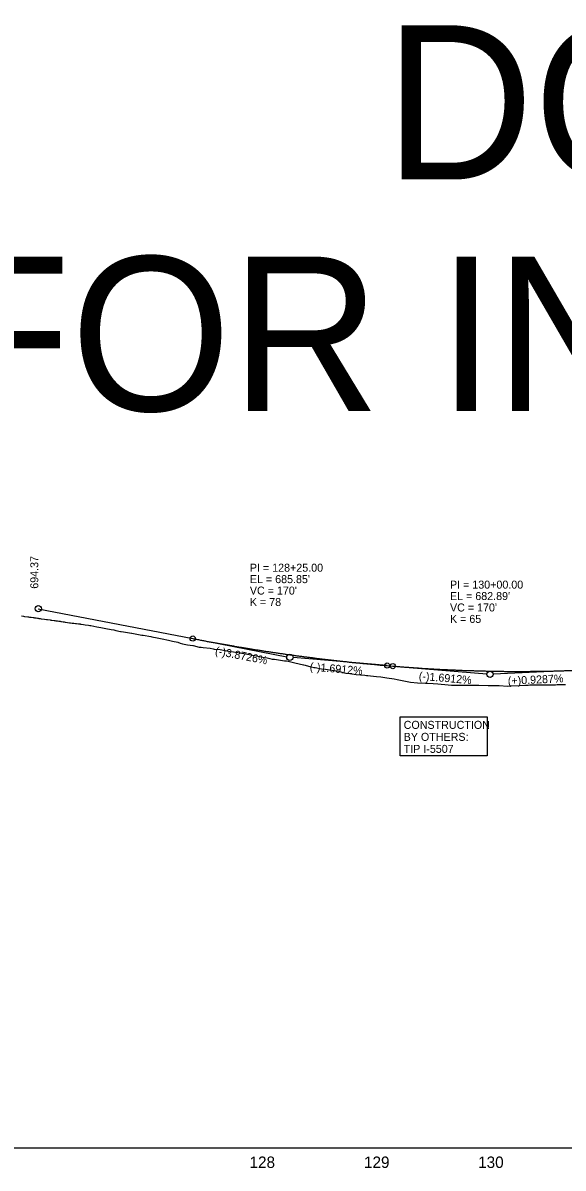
# Model space of a CAD drawing. Extents: x 1518255 to 1527303, y 471773 to 504546.
# Drawn here: x 1519662 to 1520134, y 497627 to 498629 of the extents above; entities that cross this region are included whole.
import ezdxf

# ---------------------------------------------------------------- set-up
doc = ezdxf.new("R2010")
doc.units = 0
for name, color, linetype in [('Default', 7, 'Continuous'), ('Exist Profile Cell', 7, 'Continuous'), ('Exist Vertical Profile Ground Line', 7, 'Continuous'), ('Exist Vertical Profile Horizontal Axis Label Major', 7, 'Continuous'), ('Prop Grid Mask', 7, 'Continuous'), ('Prop Vertical Profile Curve Label', 7, 'Continuous'), ('Prop Vertical Profile Grade Label', 7, 'Continuous'), ('Prop VPI Label', 7, 'Continuous')]:
    doc.layers.add(name, color=color, linetype=linetype)

msp = doc.modelspace()

# ---------------------------------------------------------------- linework, layer by layer
at = {"layer": 'Exist Profile Cell'}
msp.add_line((1519570.4, 497645), (1521670.4, 497645), dxfattribs=at)
at = {"layer": 'Exist Vertical Profile Ground Line'}
msp.add_lwpolyline([(1519660.8, 498110.5), (1519662.4, 498110.2), (1519663.3, 498110.1), (1519666.2, 498109.7), (1519666.7, 498109.7), (1519667.6, 498109.5), (1519669.1, 498109.3), (1519670.8, 498109.1), (1519671.5, 498109), (1519672, 498108.9), (1519673.6, 498108.7), (1519674.8, 498108.5), (1519675.2, 498108.5), (1519675.8, 498108.4), (1519676.5, 498108.3), (1519677, 498108.2), (1519677.8, 498108.1), (1519680.8, 498107.7), (1519682.5, 498107.4), (1519683.5, 498107.3), (1519685.7, 498107), (1519686.4, 498106.9), (1519687.3, 498106.8), (1519689.3, 498106.5), (1519689.8, 498106.4), (1519690.7, 498106.3), (1519691.7, 498106.2), (1519692.2, 498106.1), (1519693.5, 498105.9), (1519694.4, 498105.8), (1519695.1, 498105.7), (1519695.7, 498105.6), (1519697.2, 498105.4), (1519698, 498105.3), (1519699, 498105.1), (1519700.8, 498104.9), (1519702.7, 498104.6), (1519703.3, 498104.6), (1519703.7, 498104.5), (1519704.9, 498104.3), (1519705.7, 498104.3), (1519706.3, 498104.2), (1519706.6, 498104.1), (1519707.9, 498104), (1519708.9, 498103.8), (1519710.7, 498103.6), (1519711, 498103.6), (1519711.9, 498103.5), (1519712.3, 498103.4), (1519712.9, 498103.2), (1519715, 498103), (1519716.5, 498102.8), (1519719.2, 498102.3), (1519720.5, 498102.2), (1519721.2, 498102), (1519726.7, 498101), (1519730.1, 498100.3), (1519734.6, 498099.5), (1519739, 498098.6), (1519741.4, 498098.2), (1519743.2, 498097.9), (1519747.4, 498096.9), (1519748, 498096.8), (1519750, 498096.6), (1519756.9, 498095.3), (1519757.3, 498095.4), (1519764.4, 498094), (1519765.8, 498093.8), (1519767, 498093.6), (1519773.7, 498092.4), (1519774.8, 498092.2), (1519779.3, 498091.4), (1519782.2, 498090.8), (1519783.7, 498090.5), (1519789.2, 498089.4), (1519792.7, 498088.4), (1519797.5, 498087.6), (1519799.6, 498086.7), (1519801.5, 498086.1), (1519806, 498085.1), (1519808.1, 498085), (1519810.5, 498084.6), (1519810.8, 498084.5), (1519816.1, 498083.3), (1519817.7, 498083.1), (1519819.6, 498082.8), (1519825.8, 498082.2), (1519828.3, 498081.7), (1519829.2, 498081.5), (1519834.3, 498081.1), (1519837.3, 498080.6), (1519838.7, 498080.3), (1519843.2, 498079.5), (1519846.2, 498079.1), (1519851.5, 498078.3), (1519855.1, 498077.6), (1519858.4, 498077), (1519864.2, 498076), (1519869.1, 498075), (1519873, 498074.2), (1519875.6, 498073.7), (1519877.8, 498073.3), (1519880, 498072.8), (1519881.9, 498072.6), (1519890.8, 498071.3), (1519892.5, 498071.1), (1519893.9, 498070.8), (1519895.2, 498070.6), (1519899.8, 498069.5), (1519907.2, 498067.8), (1519907.6, 498067.7), (1519908.7, 498067.4), (1519913.8, 498066), (1519916.9, 498065.5), (1519917.6, 498065.4), (1519923, 498064.3), (1519926.6, 498063.8), (1519935.5, 498062.6), (1519937.4, 498062.4), (1519941.6, 498060.9), (1519944.4, 498060.5), (1519947.8, 498060), (1519953.3, 498059.4), (1519960.9, 498058.7), (1519962.3, 498058.5), (1519963.5, 498058.4), (1519966, 498058.1), (1519971.2, 498057.5), (1519974.9, 498057.1), (1519980.1, 498056.3), (1519986.7, 498055.4), (1519989.1, 498054.9), (1519998, 498053.1), (1520000.9, 498052.6), (1520006.9, 498052.1), (1520014.1, 498051.6), (1520015.8, 498051.6), (1520020.8, 498051.4), (1520024.8, 498051.1), (1520033.7, 498050.3), (1520036.8, 498050), (1520042.6, 498050), (1520045.1, 498050), (1520047.5, 498049.9), (1520050.2, 498049.8), (1520051.6, 498049.8), (1520060.5, 498049.8), (1520068.9, 498049.7), (1520069.4, 498049.7), (1520076.9, 498049.6), (1520078.3, 498049.5), (1520085.7, 498049.1), (1520087.3, 498049.2), (1520088.5, 498049.3), (1520096.2, 498049.6), (1520101.4, 498049.8), (1520103.7, 498050), (1520105.1, 498050.1), (1520114.1, 498050.1), (1520123, 498050.2), (1520127.8, 498050.3), (1520129, 498050.4), (1520131.9, 498050.4), (1520136.3, 498050.4)], dxfattribs=at)
at = {"layer": 'Prop Grid Mask'}
for p, q in [((1519675.4, 498116.8), (1519810.4, 498090.7)), ((1519980.4, 498067.1), (1519985.4, 498066.6))]:
    msp.add_line(p, q, dxfattribs=at)
msp.add_lwpolyline([(1519991.9, 498022.1), (1520067.8, 498022.1), (1520067.8, 497988), (1519991.9, 497988)], close=True, dxfattribs=at)
for points in [[(1519810.4, 498090.7), (1519813.8, 498090.1), (1519817.2, 498089.4), (1519820.6, 498088.8), (1519824, 498088.1), (1519827.4, 498087.5), (1519830.8, 498086.9), (1519834.2, 498086.3), (1519837.6, 498085.7), (1519841, 498085.1), (1519844.4, 498084.5), (1519847.8, 498083.9), (1519851.2, 498083.3), (1519854.6, 498082.8), (1519858, 498082.2), (1519861.4, 498081.7), (1519864.8, 498081.1), (1519868.2, 498080.6), (1519871.6, 498080.1), (1519875, 498079.5), (1519878.4, 498079), (1519881.8, 498078.5), (1519885.2, 498078), (1519888.6, 498077.5), (1519892, 498077), (1519895.4, 498076.6), (1519898.8, 498076.1), (1519902.2, 498075.6), (1519905.6, 498075.2), (1519909, 498074.7), (1519912.4, 498074.3), (1519915.8, 498073.9), (1519919.2, 498073.4), (1519922.6, 498073), (1519926, 498072.6), (1519929.4, 498072.2), (1519932.8, 498071.8), (1519936.2, 498071.4), (1519939.6, 498071), (1519943, 498070.7), (1519946.4, 498070.3), (1519949.8, 498069.9), (1519953.2, 498069.6), (1519956.6, 498069.3), (1519960, 498068.9), (1519963.4, 498068.6), (1519966.8, 498068.3), (1519970.2, 498068), (1519973.6, 498067.6), (1519977, 498067.4), (1519980.4, 498067.1)], [(1519985.4, 498066.6), (1519988.8, 498066.4), (1519992.2, 498066.1), (1519995.6, 498065.8), (1519999, 498065.6), (1520002.4, 498065.3), (1520005.8, 498065.1), (1520009.2, 498064.8), (1520012.6, 498064.6), (1520016, 498064.4), (1520019.4, 498064.2), (1520022.8, 498064), (1520026.2, 498063.8), (1520029.6, 498063.7), (1520033, 498063.5), (1520036.4, 498063.3), (1520039.8, 498063.2), (1520043.2, 498063), (1520046.6, 498062.9), (1520050, 498062.8), (1520053.4, 498062.7), (1520056.8, 498062.6), (1520060.2, 498062.5), (1520063.6, 498062.4), (1520067, 498062.3), (1520070.4, 498062.2), (1520073.8, 498062.2), (1520077.2, 498062.1), (1520080.6, 498062.1), (1520084, 498062), (1520087.4, 498062), (1520090.8, 498062), (1520094.2, 498062), (1520097.6, 498062), (1520101, 498062), (1520104.4, 498062), (1520107.8, 498062.1), (1520111.2, 498062.1), (1520114.6, 498062.1), (1520118, 498062.2), (1520121.4, 498062.3), (1520124.8, 498062.3), (1520128.2, 498062.4), (1520131.6, 498062.5), (1520135, 498062.6), (1520138.4, 498062.7), (1520141.8, 498062.8), (1520145.2, 498063), (1520148.6, 498063.1), (1520152, 498063.2), (1520155.4, 498063.4)]]:
    msp.add_spline(points, degree=3, dxfattribs=at)
at = {"layer": 'Prop Vertical Profile Curve Label'}
for centre in [(1519810.4, 498090.7), (1519980.4, 498067.1), (1519985.4, 498066.6)]:
    msp.add_circle(centre, 2.25, dxfattribs=at)
at = {"layer": 'Prop VPI Label'}
for p, q in [((1519810.4, 498090.7), (1519892.7, 498074.8)), ((1519980.4, 498067.1), (1519898.2, 498074)), ((1519985.4, 498066.6), (1520067.7, 498059.7)), ((1520155.4, 498063.4), (1520073.2, 498059.6))]:
    msp.add_line(p, q, dxfattribs=at)
for centre in [(1519675.4, 498116.8), (1519895.4, 498074.2), (1520070.4, 498059.4)]:
    msp.add_circle(centre, 2.75, dxfattribs=at)

# ---------------------------------------------------------------- texts
at = {"layer": 'Default'}
for s, p in [('DO NOT LAYOUT', (1519978.3, 498492.4)), ('FOR INFORMATION ONLY', (1519593.4, 498289.9))]:
    msp.add_text(s, height=135, dxfattribs=at).set_placement(p)
at = {"layer": 'Exist Vertical Profile Horizontal Axis Label Major'}
for s, p in [('128', (1519860.1, 497627.5)), ('129', (1519960.2, 497627.5)), ('130', (1520060, 497627.5))]:
    msp.add_text(s, height=10, dxfattribs=at).set_placement(p)
at = {"layer": 'Prop Vertical Profile Curve Label'}
for s, p in [("VC = 170'", (1519860.4, 498129.2)), ('K = 78', (1519860.4, 498119.2)), ("VC = 170'", (1520035.4, 498114.4)), ('K = 65', (1520035.4, 498104.4))]:
    msp.add_text(s, height=7, dxfattribs=at).set_placement(p)
at = {"layer": 'Prop Vertical Profile Grade Label'}
for s, rotation, p in [('(-)3.8726%', 349.0415, (1519829.6, 498076.8)), ('(-)1.6912%', 355.1665, (1519912.6, 498062.8)), ('(-)1.6912%', 355.1665, (1520007.9, 498054.7)), ('(+)0.9287%', 2.6587, (1520086.1, 498050.2))]:
    msp.add_text(s, height=7, rotation=rotation, dxfattribs=at).set_placement(p)
at = {"layer": 'Prop VPI Label'}
msp.add_text('694.37', height=7, rotation=90, dxfattribs=at).set_placement((1519675.4, 498134.3))
for s, p in [('PI = 128+25.00', (1519860.4, 498149.2)), ("EL = 685.85'", (1519860.4, 498139.2)), ('PI = 130+00.00', (1520035.4, 498134.4)), ("EL = 682.89'", (1520035.4, 498124.4)), ('CONSTRUCTION', (1519994.9, 498011.7)), ('BY OTHERS:', (1519994.9, 498001.2)), ('TIP I-5507', (1519994.9, 497990.7))]:
    msp.add_text(s, height=7, dxfattribs=at).set_placement(p)

doc.saveas('drawing.dxf')
